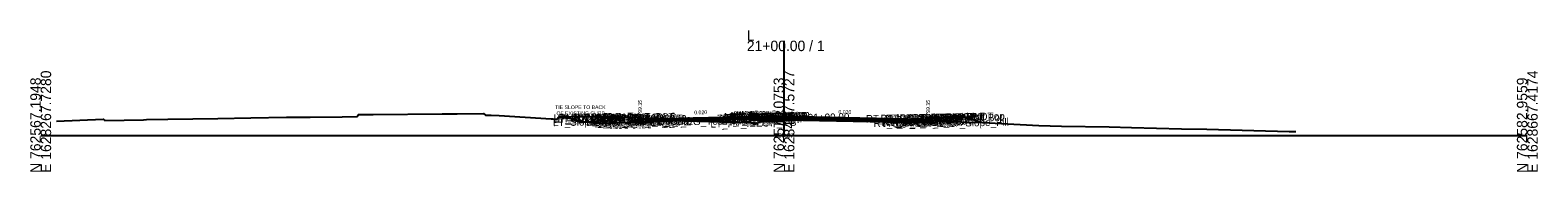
# Model space of a CAD drawing. Extents: x -26 to 4403, y -510 to 9556.
# Drawn here: x 997.2 to 1402.8, y 990.3 to 1028.3 of the extents above; entities that cross this region are included whole.
import ezdxf

# ---------------------------------------------------------------- set-up
doc = ezdxf.new("R2010")
doc.units = 0
for name, color, linetype in [('Default', 7, 'Continuous'), ('Exist CMT Pavement', 7, 'Continuous'), ('Exist Cross Section Cell', 7, 'Continuous'), ('Exist XS Center Line Elevation Label', 7, 'Continuous'), ('Exist XS Ground Line', 7, 'Continuous'), ('Prop CMT Conc Surface', 7, 'Continuous'), ('Prop CMT Concrete Structures', 7, 'Continuous'), ('Prop CMT Pvmt Course 1', 7, 'Continuous'), ('Prop CMT Pvmt Course 1 CG', 7, 'Continuous'), ('Prop CMT Pvmt Course 1 Wedge', 7, 'Continuous'), ('Prop CMT Pvmt Course 2', 7, 'Continuous'), ('Prop CMT Pvmt Course 2 Wedge', 7, 'Continuous'), ('Prop CMT Pvmt Course 3', 7, 'Continuous'), ('Prop CMT Pvmt Course 3 Wedge', 7, 'Continuous'), ('Prop CMT Pvmt Surface', 7, 'Continuous'), ('Prop CMT Pvmt Wedge Surface 1', 7, 'Continuous'), ('Prop CMT Pvmt Wedge Surface 2', 7, 'Continuous'), ('Prop CMT Pvmt Wedge Surface 3', 7, 'Continuous'), ('Prop CMT Slope Grass', 7, 'Continuous'), ('Prop CMT Subgrade Earthwork', 7, 'Continuous'), ('Prop XS Hydro Elevations', 7, 'Continuous'), ('Prop XS SE Text', 7, 'Continuous'), ('Prop XS Side Slope Text', 7, 'Continuous'), ('Scratch_Level_0', 7, 'Continuous')]:
    doc.layers.add(name, color=color, linetype=linetype)

msp = doc.modelspace()

# ---------------------------------------------------------------- linework, layer by layer
at = {"layer": 'Exist CMT Pavement'}
msp.add_lwpolyline([(1163.26, 1003.76), (1169.85, 1003.99), (1171.49, 1004.04), (1172.95, 1004), (1190.87, 1003.49)], dxfattribs=at)
at = {"layer": 'Exist Cross Section Cell'}
for p, q in [((1200, 1000), (1200, 1025.5)), ((1000, 1000), (1200, 1000)), ((1200, 1000), (1400, 1000))]:
    msp.add_line(p, q, dxfattribs=at)
at = {"layer": 'Exist XS Ground Line'}
msp.add_lwpolyline([(1004.27, 1003.91), (1016.8, 1004.41), (1017.29, 1004.1), (1027.66, 1004.25), (1028.5, 1004.3), (1034.22, 1004.39), (1047.64, 1004.63), (1056.5, 1004.75), (1066.15, 1004.94), (1072.49, 1004.98), (1081.13, 1005.05), (1085.11, 1005.14), (1085.52, 1005.64), (1089.44, 1005.64), (1108.02, 1005.86), (1112.05, 1005.9), (1119.17, 1005.96), (1119.67, 1005.46), (1121.17, 1005.54), (1123.33, 1005.41), (1137.35, 1004.54), (1137.93, 1004.51), (1138.85, 1004.47), (1139.35, 1004.97), (1142.11, 1004.7), (1142.51, 1004.6), (1142.87, 1004.52), (1145.78, 1003.74), (1148.79, 1003.71), (1149.23, 1003.71), (1149.77, 1003.29), (1169.85, 1003.99), (1171.49, 1004.04), (1172.95, 1004), (1190.87, 1003.49), (1192, 1003.39), (1192.8, 1003.32), (1193.42, 1003.74), (1194.02, 1003.76), (1198.35, 1003.88), (1200, 1004.07), (1206.73, 1004.41), (1214.84, 1004.27), (1216.42, 1004.24), (1218.16, 1004.19), (1229.27, 1004.24), (1233, 1004.22), (1237.33, 1004.15), (1249.62, 1003.66), (1253.49, 1003.54), (1268.61, 1002.75), (1274.66, 1002.56), (1287.49, 1002.33), (1293.52, 1002.16), (1306.96, 1001.8), (1313.74, 1001.73), (1335.95, 1001.13), (1337.76, 1001.08)], dxfattribs=at)
at = {"layer": 'Prop CMT Conc Surface'}
for points in [[(1156.75, 1004.94), (1151.75, 1005.04)], [(1161.25, 1004.35), (1161.25, 1004.85), (1160.75, 1004.85)], [(1163.25, 1004.47), (1161.25, 1004.35)], [(1236.75, 1004.47), (1238.75, 1004.35)], [(1238.75, 1004.35), (1238.75, 1004.85), (1239.25, 1004.85)], [(1243.25, 1004.94), (1248.25, 1005.04)]]:
    msp.add_lwpolyline(points, dxfattribs=at)
at = {"layer": 'Prop CMT Concrete Structures'}
for points in [[(1151.75, 1004.71), (1151.75, 1005.04)], [(1151.75, 1005.04), (1156.75, 1004.94)], [(1156.75, 1004.61), (1151.75, 1004.71)], [(1156.75, 1004.94), (1156.75, 1004.61)], [(1163.25, 1004.47), (1161.25, 1004.35), (1161.25, 1004.85), (1160.75, 1004.85)], [(1160.75, 1004.85), (1160.75, 1003.84), (1163.25, 1003.89)], [(1163.25, 1003.89), (1163.25, 1004.47)], [(1196, 1005.29), (1195.99, 1005.45), (1195.24, 1005.7), (1194, 1005.73), (1192.76, 1005.46), (1192.01, 1005.21), (1192, 1005.04)], [(1192, 1005.04), (1196, 1005.29)], [(1236.75, 1004.47), (1238.75, 1004.35), (1238.75, 1004.85), (1239.25, 1004.85)], [(1239.25, 1004.85), (1239.25, 1003.84), (1236.75, 1003.89)], [(1236.75, 1003.89), (1236.75, 1004.47)], [(1248.25, 1005.04), (1243.25, 1004.94)], [(1243.25, 1004.94), (1243.25, 1004.61)], [(1243.25, 1004.61), (1248.25, 1004.71)], [(1248.25, 1004.71), (1248.25, 1005.04)]]:
    msp.add_lwpolyline(points, dxfattribs=at)
at = {"layer": 'Prop CMT Pvmt Course 1'}
for points in [[(1192, 1005.04), (1163.25, 1004.47)], [(1163.25, 1004.34), (1192, 1004.92)], [(1163.25, 1004.47), (1163.25, 1004.22), (1163.25, 1004.22), (1163.25, 1004.34)], [(1192, 1005.04), (1196, 1005.29)], [(1196, 1005.04), (1192, 1004.79)], [(1192, 1004.79), (1192, 1005.04)], [(1192, 1004.79), (1192, 1005.04)], [(1192, 1004.92), (1192, 1004.79), (1192, 1004.79)], [(1196, 1005.29), (1196, 1005.04)], [(1196, 1005.29), (1236.75, 1004.47)], [(1196, 1005.04), (1196, 1005.29)], [(1236.75, 1004.22), (1196, 1005.04)], [(1236.75, 1004.47), (1236.75, 1004.22)]]:
    msp.add_lwpolyline(points, dxfattribs=at)
msp.add_lwpolyline([(1196, 1005.04), (1196, 1005.16), (1196, 1005.16), (1196, 1005.04)], close=True, dxfattribs=at)
at = {"layer": 'Prop CMT Pvmt Course 1 CG'}
for points in [[(1163.25, 1003.89), (1160.25, 1003.83), (1159.91, 1003.49)], [(1159.91, 1003.49), (1163.25, 1003.55)], [(1163.25, 1003.55), (1163.25, 1003.89)], [(1236.75, 1003.89), (1239.75, 1003.83), (1240.09, 1003.49)], [(1236.75, 1003.55), (1236.75, 1003.89)], [(1240.09, 1003.49), (1236.75, 1003.55)]]:
    msp.add_lwpolyline(points, dxfattribs=at)
at = {"layer": 'Prop CMT Pvmt Course 1 Wedge'}
for points in [[(1163.25, 1004.34), (1169.85, 1004.48), (1171.49, 1004.51), (1172.95, 1004.54), (1190.87, 1004.9), (1192, 1004.92)], [(1192, 1004.79), (1190.87, 1004.77), (1172.95, 1004.41), (1171.49, 1004.38), (1169.85, 1004.35), (1163.25, 1004.22)], [(1163.25, 1004.22), (1163.25, 1004.34)], [(1192, 1004.92), (1192, 1004.79)]]:
    msp.add_lwpolyline(points, dxfattribs=at)
at = {"layer": 'Prop CMT Pvmt Course 2'}
for points in [[(1163.25, 1003.89), (1163.25, 1003.89), (1163.25, 1004.22), (1163.25, 1004.22)], [(1163.25, 1004.22), (1163.25, 1003.89)], [(1192, 1004.79), (1196, 1005.04)], [(1192, 1004.46), (1192, 1004.79)], [(1196, 1004.7), (1192, 1004.46)], [(1196, 1005.04), (1196, 1004.7)], [(1196, 1004.7), (1196, 1005.04)], [(1196, 1005.04), (1236.75, 1004.22)], [(1236.75, 1003.89), (1196, 1004.7)], [(1236.75, 1004.22), (1236.75, 1003.89)]]:
    msp.add_lwpolyline(points, dxfattribs=at)
at = {"layer": 'Prop CMT Pvmt Course 2 Wedge'}
for points in [[(1163.25, 1004.22), (1169.85, 1004.35), (1171.49, 1004.38), (1172.95, 1004.41), (1190.87, 1004.77), (1192, 1004.79)], [(1192, 1004.46), (1190.87, 1004.44), (1172.95, 1004.08), (1171.49, 1004.05), (1169.85, 1004.02), (1163.25, 1003.89)], [(1163.25, 1003.89), (1163.25, 1004.22)], [(1192, 1004.79), (1192, 1004.46)]]:
    msp.add_lwpolyline(points, dxfattribs=at)
at = {"layer": 'Prop CMT Pvmt Course 3'}
for points in [[(1163.25, 1003.89), (1163.25, 1003.89), (1163.25, 1003.55), (1163.25, 1003.55)], [(1163.25, 1003.55), (1163.25, 1003.89)], [(1192, 1004.46), (1196, 1004.7)], [(1192, 1004.13), (1192, 1004.46)], [(1196, 1004.37), (1192, 1004.13)], [(1196, 1004.7), (1196, 1004.37)], [(1196, 1004.7), (1236.75, 1003.89)], [(1196, 1004.37), (1196, 1004.7)], [(1236.75, 1003.55), (1196, 1004.37)], [(1236.75, 1003.89), (1236.75, 1003.55)]]:
    msp.add_lwpolyline(points, dxfattribs=at)
at = {"layer": 'Prop CMT Pvmt Course 3 Wedge'}
for points in [[(1163.25, 1003.89), (1169.85, 1004.02), (1171.49, 1004.05), (1172.95, 1004.08), (1190.87, 1004.44), (1192, 1004.46)], [(1192, 1003.39), (1190.87, 1003.49), (1172.95, 1004), (1171.49, 1004.04), (1169.85, 1003.99), (1163.25, 1003.76)], [(1163.25, 1003.76), (1163.25, 1003.89)]]:
    msp.add_lwpolyline(points, dxfattribs=at)
at = {"layer": 'Prop CMT Pvmt Surface'}
for points in [[(1192, 1005.04), (1163.25, 1004.47)], [(1192, 1005.04), (1196, 1005.29)], [(1196, 1005.29), (1236.75, 1004.47)]]:
    msp.add_lwpolyline(points, dxfattribs=at)
at = {"layer": 'Prop CMT Pvmt Wedge Surface 1'}
for points in [[(1192, 1004.92), (1163.25, 1004.34)], [(1163.25, 1004.22), (1163.25, 1004.47)], [(1163.25, 1004.34), (1163.25, 1004.22), (1163.25, 1004.22)], [(1192, 1005.04), (1192, 1004.79), (1192, 1004.79), (1192, 1004.92)]]:
    msp.add_lwpolyline(points, dxfattribs=at)
at = {"layer": 'Prop CMT Pvmt Wedge Surface 2'}
for points in [[(1192, 1004.79), (1163.25, 1004.22)], [(1163.25, 1004.22), (1163.25, 1004.47)], [(1192, 1005.04), (1192, 1004.79)]]:
    msp.add_lwpolyline(points, dxfattribs=at)
at = {"layer": 'Prop CMT Pvmt Wedge Surface 3'}
for points in [[(1163.25, 1003.89), (1163.25, 1004.47)], [(1192, 1004.46), (1163.25, 1003.89)], [(1192, 1005.04), (1192, 1004.46)]]:
    msp.add_lwpolyline(points, dxfattribs=at)
at = {"layer": 'Prop CMT Slope Grass'}
for points in [[(1160.75, 1004.85), (1151.25, 1005.04), (1139.35, 1004.97)], [(1239.25, 1004.85), (1248.25, 1005.03)], [(1248.25, 1005.03), (1248.75, 1005.04), (1253.21, 1003.55)]]:
    msp.add_lwpolyline(points, dxfattribs=at)
at = {"layer": 'Prop CMT Subgrade Earthwork'}
msp.add_line((1190.87, 1004.11), (1190.87, 1003.49), dxfattribs=at)
for points in [[(1163.25, 1003.55), (1159.91, 1003.49), (1158.5, 1004.89)], [(1163.25, 1003.55), (1163.26, 1003.76)], [(1163.25, 1003.55), (1163.25, 1003.55)], [(1192, 1004.13), (1190.87, 1004.11), (1190.87, 1004.11)], [(1192, 1004.13), (1196, 1004.37)], [(1196, 1004.37), (1236.75, 1003.55)], [(1236.75, 1003.55), (1240.09, 1003.49), (1241.5, 1004.89)]]:
    msp.add_lwpolyline(points, dxfattribs=at)

# ---------------------------------------------------------------- texts
at = {"layer": 'Default'}
msp.add_text('-', height=0.0001, dxfattribs=at).set_placement((1000, 1000))
at = {"layer": 'Exist Cross Section Cell'}
for s, p in [('L', (1190, 1025.5)), ('21+00.00 / 1', (1190, 1022.7))]:
    msp.add_text(s, height=2.8, dxfattribs=at).set_placement(p)
for s, p in [('N 762567.1948', (1000, 990)), ('E 1628267.7280', (1002.8, 990)), ('N 762575.0753', (1200, 990)), ('E 1628467.5727', (1202.8, 990)), ('N 762582.9559', (1400, 990)), ('E 1628667.4174', (1402.8, 990))]:
    msp.add_text(s, height=2.8, rotation=90, dxfattribs=at).set_placement(p)
at = {"layer": 'Exist XS Center Line Elevation Label'}
msp.add_text('799.07', height=1.2, dxfattribs=at).set_placement((1197.54, 999.47))
at = {"layer": 'Prop XS Hydro Elevations'}
for p in [(1161.75, 1005.35), (1239.25, 1005.35)]:
    msp.add_text('799.35', height=1, rotation=90, dxfattribs=at).set_placement(p)
at = {"layer": 'Prop XS SE Text'}
for rotation, p in [(1.1458, (1175.86, 1005.72)), (358.8542, (1214.65, 1005.91))]:
    msp.add_text('0.020', height=1, rotation=rotation, dxfattribs=at).set_placement(p)
at = {"layer": 'Prop XS Side Slope Text'}
for s, p in [('TIE SLOPE TO BACK', (1138.42, 1007.13)), ('OF EXISTING CURB', (1138.78, 1005.51))]:
    msp.add_text(s, height=1, dxfattribs=at).set_placement(p)
msp.add_text('3:1', height=1, rotation=341.5651, dxfattribs=at).set_placement((1250.6, 1005.05))
at = {"layer": 'Scratch_Level_0'}
for s, p in [('LT_SDWK_Out_Top', (1138.01, 1003.76)), ('LT_Sub_Trench_Out_DLT', (1139.09, 1003.51)), ('LT_CSLP_Pnt', (1141.45, 1003.84)), ('LT_PV1_IEEOP', (1182.54, 1003.73)), ('LT_PV1_PGL', (1183.8, 1003.88)), ('MI_Face In', (1183.92, 1004.05)), ('RT_PV2_OEEOP', (1185.28, 1003.82)), ('MI_Top In', (1185.63, 1004.32)), ('21+00.00', (1185.76, 1003.95)), ('RT_PV1_OEEOP', (1185.85, 1003.96)), ('RT_PV2_IEEOP', (1185.93, 1003.83)), ('MI_Face Out', (1186.28, 1004.26)), ('21+00.00', (1186.44, 1004.31)), ('MI_Top Out', (1186.49, 1004.53)), ('RT_PV1_IEEOP', (1186.49, 1003.97)), ('RT_PV2_PGL1', (1186.86, 1003.85)), ('21+00.00', (1186.97, 1004.43)), ('MI_Crown', (1187.09, 1004.59)), ('RT_PV2_PGL', (1187.19, 1003.86)), ('MI_Bot Out', (1187.28, 1004.11)), ('RT_PV1_PGL', (1187.75, 1004.12)), ('21+00.00', (1189.3, 1004.47)), ('21+00.00', (1189.75, 1004.23)), ('RT_Sub_Trench_Out_DLT', (1222.04, 1003.51)), ('RT_SDWK_In_Top', (1231.08, 1003.7)), ('RT_SDWK_Out_Top', (1234.46, 1003.76)), ('RT_Shld_O', (1240.81, 1003.88)), ('CSLP_Pnt', (1241.64, 1003.9)), ('21+00.00', (1242.35, 1003.91)), ('LT_Slope_Fill', (1137.85, 1002.54)), ('LT_SDWK_Out_Bot', (1138.04, 1003.43)), ('LT_SDWK_In_Top', (1144.63, 1003.7)), ('LT_SDWK_In_Bot', (1144.66, 1003.36)), ('LT_CG1_Shelf_Out', (1146.82, 1002.56)), ('LT_PV_Sub_Tie_Out', (1148.23, 1002.46)), ('LT_CG_Top_Face', (1148.53, 1003.6)), ('LT_CG_Top_BOC', (1149.05, 1003.62)), ('LT_CG_Bot_BOC', (1149.09, 1002.6)), ('LT_CG_Top_Gut', (1149.51, 1003.11)), ('LT_Sub_OEOP', (1150.04, 1002.29)), ('LT_Sub_OEOT_CG', (1150.64, 1002.3)), ('LT_PV_OEEOP_EG', (1150.82, 1002.51)), ('LT_Sub_OEEOP', (1152.48, 1002.34)), ('LT_PV2_OEEOP', (1152.58, 1003.01)), ('LT_PV3_OEEOP', (1152.58, 1002.67)), ('21+00.00', (1153.15, 1003.75)), ('LT_PV1_OEEOP', (1153.15, 1003.14)), ('LT_CG_Bot_IE', (1153.19, 1002.68)), ('LT_Sub_OEOT', (1153.35, 1002.35)), ('LT_PV2_OEOT', (1153.44, 1003.02)), ('LT_PV3_OEOT', (1153.44, 1002.69)), ('LT_PV1_OEOT', (1154.01, 1003.29)), ('21+00.00', (1154.68, 1003.72)), ('LT_PV_EG_TestPt', (1164.06, 1002.6)), ('LT_PV_IEEOP_EG', (1180.21, 1002.16)), ('LT_PV2_IEEOP', (1181.97, 1003.59)), ('LT_PV3_IEEOP', (1181.97, 1003.26)), ('LT_PV2_PGL1', (1182.9, 1003.61)), ('LT_PV3_PGL1', (1182.9, 1003.28)), ('LT_PV2_PGL', (1183.23, 1003.62)), ('LT_PV3_PGL', (1183.23, 1003.29)), ('LT_PV4_PGL', (1183.23, 1002.95)), ('RT_Sub_OEEOP', (1185.19, 1003.15)), ('RT_PV3_OEEOP', (1185.28, 1003.49)), ('RT_PV3_PGL1', (1186.86, 1003.52)), ('RT_PV4_PGL', (1187.19, 1003.19)), ('21+00.00', (1206.4, 1003.83)), ('RT_Sub_OEOT_CG', (1224.1, 1002.3)), ('RT_CG_Top_Face', (1225.99, 1003.59)), ('RT_CG1_Shelf_Out', (1226.28, 1002.56)), ('RT_CG_Bot_IE', (1226.64, 1002.68)), ('RT_Sub_OEOT', (1226.8, 1002.35)), ('RT_PV2_OEOT', (1226.9, 1003.02)), ('RT_PV3_OEOT', (1226.9, 1002.69)), ('RT_CG_Top_Gut', (1226.96, 1003.11)), ('RT_PV1_OEOT', (1227.46, 1003.28)), ('RT_CG_Top_BOC', (1227.51, 1003.61)), ('RT_CG_Bot_BOC', (1227.54, 1002.6)), ('RT_Sub_OEOP', (1230.18, 1002.29)), ('RT_SDWK_In_Bot', (1231.11, 1003.36)), ('21+00.00', (1232.89, 1003.72)), ('21+00.00', (1233.3, 1003.73)), ('RT_SDWK_Out_Bot', (1234.49, 1003.43)), ('21+00.00', (1236.12, 1003.79)), ('RT_Slope_Fill', (1243.71, 1002.36))]:
    msp.add_text(s, height=2, rotation=1.1458, dxfattribs=at).set_placement(p)

doc.saveas('drawing.dxf')
